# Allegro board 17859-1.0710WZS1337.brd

Outline 225.31 x 110 mm; copper layers: TOP, L2GND, L3, L4, L5VCC, L6, L7GND, BOTTOM. Coordinates in mm from the lower left corner of the outline.

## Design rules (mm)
constraint set DEFAULT: min track width 0.127, pair gap 0.102
net group 65982D_AUX-DIFF1: nets 65982D_AUXN 65982D_AUXP
net group BT_USB20_CON_N: nets BT_USB20_CON_N BT_USB20_N
net group BT_USB20_CON_P: nets BT_USB20_CON_P BT_USB20_P
net group CNV_WR_CLKN: nets CNV_WR_CLKN CNV_WR_CLKN_R
net group CNV_WR_CLKP: nets CNV_WR_CLKP CNV_WR_CLKP_R
net group CNV_WR_DN0: nets CNV_WR_DN0 CNV_WR_DN0_R
net group CNV_WR_DN1: nets CNV_WR_DN1 CNV_WR_DN1_R
net group CNV_WR_DP0: nets CNV_WR_DP0 CNV_WR_DP0_R
net group CNV_WR_DP1: nets CNV_WR_DP1 CNV_WR_DP1_R
net group CNV_WT_CLKN: nets CNV_WT_CLKN CNV_WT_CLKN_R
net group CNV_WT_CLKP: nets CNV_WT_CLKP CNV_WT_CLKP_R
net group CNV_WT_DN0: nets CNV_WT_DN0 CNV_WT_DN0_R
net group CNV_WT_DN1: nets CNV_WT_DN1 CNV_WT_DN1_R
net group CNV_WT_DP0: nets CNV_WT_DP0 CNV_WT_DP0_R
net group CNV_WT_DP1: nets CNV_WT_DP1 CNV_WT_DP1_R
net group DDR4_A_BA_40-MW: nets M_A_BA0 M_A_BA1
net group DDR4_A_BG_40-MW: nets M_A_BG0 M_A_BG1
net group DDR4_A_ODT: nets M_A_DIMA_ODT0 M_A_DIMA_ODT1
net group DDR4_B_BA_40-MW: nets M_B_BA0 M_B_BA1
net group DDR4_B_BG_40-MW: nets M_B_BG0 M_B_BG1
net group DDR4_B_ODT: nets M_B_DIMB_ODT0 M_B_DIMB_ODT1
net group DP2_AUX_CPU_N: nets DP2_AUX_C_N DP2_AUX_CPU_N
net group DP2_AUX_CPU_P: nets DP2_AUX_C_P DP2_AUX_CPU_P
net group DP2_DDI_TX_N0: nets DP2_DDI_TX_N0 DP2_DDI_TX_RE_C_N0
net group DP2_DDI_TX_N1: nets DP2_DDI_TX_N1 DP2_DDI_TX_RE_C_N1
net group DP2_DDI_TX_N2: nets DP2_DDI_TX_N2 DP2_DDI_TX_RE_C_N2
net group DP2_DDI_TX_N3: nets DP2_DDI_TX_N3 DP2_DDI_TX_RE_C_N3
net group DP2_DDI_TX_P0: nets DP2_DDI_TX_P0 DP2_DDI_TX_RE_C_P0
net group DP2_DDI_TX_P1: nets DP2_DDI_TX_P1 DP2_DDI_TX_RE_C_P1
net group DP2_DDI_TX_P2: nets DP2_DDI_TX_P2 DP2_DDI_TX_RE_C_P2
net group DP2_DDI_TX_P3: nets DP2_DDI_TX_P3 DP2_DDI_TX_RE_C_P3
net group EDP_AUX_CON_N: nets EDP_AUX_CON_N EDP_AUX_CPU_N
net group EDP_AUX_CON_P: nets EDP_AUX_CON_P EDP_AUX_CPU_P
net group EDP_TX_CON_N0: nets EDP_TX_CON_N0 EDP_TX_CPU_N0
net group EDP_TX_CON_N1: nets EDP_TX_CON_N1 EDP_TX_CPU_N1
net group EDP_TX_CON_P0: nets EDP_TX_CON_P0 EDP_TX_CPU_P0
net group EDP_TX_CON_P1: nets EDP_TX_CON_P1 EDP_TX_CPU_P1
net group GFX_PCIE_RX_C_N0: nets GFX_PCIE_RX_C_N0 GFX_PCIE_RX_N0
net group GFX_PCIE_RX_C_N1: nets GFX_PCIE_RX_C_N1 GFX_PCIE_RX_N1
net group GFX_PCIE_RX_C_N2: nets GFX_PCIE_RX_C_N2 GFX_PCIE_RX_N2
net group GFX_PCIE_RX_C_N3: nets GFX_PCIE_RX_C_N3 GFX_PCIE_RX_N3
net group GFX_PCIE_RX_C_P0: nets GFX_PCIE_RX_C_P0 GFX_PCIE_RX_P0
net group GFX_PCIE_RX_C_P1: nets GFX_PCIE_RX_C_P1 GFX_PCIE_RX_P1
net group GFX_PCIE_RX_C_P2: nets GFX_PCIE_RX_C_P2 GFX_PCIE_RX_P2
net group GFX_PCIE_RX_C_P3: nets GFX_PCIE_RX_C_P3 GFX_PCIE_RX_P3
net group GFX_PCIE_TX_C_N0: nets GFX_PCIE_TX_C_N0 GFX_PCIE_TX_N0
net group GFX_PCIE_TX_C_N1: nets GFX_PCIE_TX_C_N1 GFX_PCIE_TX_N1
net group GFX_PCIE_TX_C_N2: nets GFX_PCIE_TX_C_N2 GFX_PCIE_TX_N2
net group GFX_PCIE_TX_C_N3: nets GFX_PCIE_TX_C_N3 GFX_PCIE_TX_N3
net group GFX_PCIE_TX_C_P0: nets GFX_PCIE_TX_C_P0 GFX_PCIE_TX_P0
net group GFX_PCIE_TX_C_P1: nets GFX_PCIE_TX_C_P1 GFX_PCIE_TX_P1
net group GFX_PCIE_TX_C_P2: nets GFX_PCIE_TX_C_P2 GFX_PCIE_TX_P2
net group GFX_PCIE_TX_C_P3: nets GFX_PCIE_TX_C_P3 GFX_PCIE_TX_P3
net group GND: nets 65982D_GND MIC_GND
net group HDMI_DDI_TX_CMC_N0: nets HDMI_DDI_TX_CMC_N0 HDMI_DDI_TX_N0
net group HDMI_DDI_TX_CMC_N1: nets HDMI_DDI_TX_CMC_N1 HDMI_DDI_TX_N1
net group HDMI_DDI_TX_CMC_N2: nets HDMI_DDI_TX_CMC_N2 HDMI_DDI_TX_N2
net group HDMI_DDI_TX_CMC_N3: nets HDMI_DDI_TX_CMC_N3 HDMI_DDI_TX_N3
net group HDMI_DDI_TX_CMC_P0: nets HDMI_DDI_TX_CMC_P0 HDMI_DDI_TX_P0
net group HDMI_DDI_TX_CMC_P1: nets HDMI_DDI_TX_CMC_P1 HDMI_DDI_TX_P1
net group HDMI_DDI_TX_CMC_P2: nets HDMI_DDI_TX_CMC_P2 HDMI_DDI_TX_P2
net group HDMI_DDI_TX_CMC_P3: nets HDMI_DDI_TX_CMC_P3 HDMI_DDI_TX_P3
net group LAN_CLK_CPU-DIFF1: nets LAN_CLK_CPU_N LAN_CLK_CPU_P
net group LAN_PCIE_RX-DIFF1: nets LAN_PCIE_RX_N LAN_PCIE_RX_P
net group LAN_PCIE_TX_C_N: nets LAN_PCIE_TX_C_N LAN_PCIE_TX_N
net group LAN_PCIE_TX_C_P: nets LAN_PCIE_TX_C_P LAN_PCIE_TX_P
net group NTP_GFX_CLK_CPU-DIFF1: nets GFX_CLK_CPU_N GFX_CLK_CPU_P
net group NTP_M_A_CLK0-DIFF1: nets M_A_CLK0 M_A_CLK#0
net group NTP_M_A_CLK1-DIFF1: nets M_A_CLK1 M_A_CLK#1
net group NTP_M_A_DQS0-DIFF1: nets M_A_DQS_DN0 M_A_DQS_DP0
net group NTP_M_A_DQS1-DIFF1: nets M_A_DQS_DN1 M_A_DQS_DP1
net group NTP_M_A_DQS2-DIFF1: nets M_A_DQS_DN2 M_A_DQS_DP2
net group NTP_M_A_DQS3-DIFF1: nets M_A_DQS_DN3 M_A_DQS_DP3
net group NTP_M_A_DQS4-DIFF1: nets M_A_DQS_DN4 M_A_DQS_DP4
net group NTP_M_A_DQS5-DIFF1: nets M_A_DQS_DN5 M_A_DQS_DP5
net group NTP_M_A_DQS6-DIFF1: nets M_A_DQS_DN6 M_A_DQS_DP6
net group NTP_M_A_DQS7-DIFF1: nets M_A_DQS_DN7 M_A_DQS_DP7
net group NTP_M_B_CLK0-DIFF1: nets M_B_CLK0 M_B_CLK#0
net group NTP_M_B_CLK1-DIFF1: nets M_B_CLK1 M_B_CLK#1
net group NTP_M_B_DQS0-DIFF1: nets M_B_DQS_DN0 M_B_DQS_DP0
net group NTP_M_B_DQS1-DIFF1: nets M_B_DQS_DN1 M_B_DQS_DP1
net group NTP_M_B_DQS2-DIFF1: nets M_B_DQS_DN2 M_B_DQS_DP2
net group NTP_M_B_DQS3-DIFF1: nets M_B_DQS_DN3 M_B_DQS_DP3
net group NTP_M_B_DQS4-DIFF1: nets M_B_DQS_DN4 M_B_DQS_DP4
net group NTP_M_B_DQS5-DIFF1: nets M_B_DQS_DN5 M_B_DQS_DP5
net group NTP_M_B_DQS6-DIFF1: nets M_B_DQS_DN6 M_B_DQS_DP6
net group NTP_M_B_DQS7-DIFF1: nets M_B_DQS_DN7 M_B_DQS_DP7
net group NTP_VRAM_A_WCK01-DIFF1: nets FBA_WCK01 FBA_WCK01#
net group NTP_VRAM_A_WCK45-DIFF1: nets FBA_WCK45 FBA_WCK45#
net group NTP_VRAM_A_WCK67-DIFF1: nets FBA_WCK67 FBA_WCK67#
net group NTP_VRAM_CLK_A0-DIFF1: nets FBA_CLK0N FBA_CLK0P
net group NTP_VRAM_CLK_A1-DIFF1: nets FBA_CLK1N FBA_CLK1P
net group NTP_VRAM_S_WCK23-DIFF1: nets FBA_WCK23 FBA_WCK23#
net group PCIE_RCOMP-DIFF: nets PCIE_RCOMPN PCIE_RCOMPP
net group POWER_40M_POWER: nets HVA_GATE1 HVA_GATE2
net group POWER_160M: nets RT8812_PVCC VGACORE_VDD_SENSE_1
net group SENSE_VCORE-DIFF: nets VCC_SENSE VSS_SENSE
net group SENSE_VGT-DIFF: nets VCCGT_SENSE VSSGT_SENSE
net group SSD_PCIE_RX1-DIFF1: nets SSD_PCIE_RX_N1 SSD_PCIE_RX_P1
net group SSD_PCIE_TX_CON_N1: nets SSD_PCIE_TX_CON_N1 SSD_PCIE_TX_N1
net group SSD_PCIE_TX_CON_N2: nets SSD_PCIE_TX_CON_N2 SSD_PCIE_TX_N2
net group SSD_PCIE_TX_CON_N3: nets SSD_PCIE_TX_CON_N3 SSD_PCIE_TX_N3
net group SSD_PCIE_TX_CON_P1: nets SSD_PCIE_TX_CON_P1 SSD_PCIE_TX_P1
net group SSD_PCIE_TX_CON_P2: nets SSD_PCIE_TX_CON_P2 SSD_PCIE_TX_P2
net group SSD_PCIE_TX_CON_P3: nets SSD_PCIE_TX_CON_P3 SSD_PCIE_TX_P3
net group TBTA_SENSE-DIFF1: nets TBTA_SENSEN TBTA_SENSEP
net group THERM_7718-DIFF1: nets NCT7718_DXN NCT7718_DXP
net group TYPE_C_12M: nets USB1_CC1 USB1_CC2
net group USB1_PN1_R: nets USB1_PN1_R USB1_USB20_CON_N
net group USB1_PP1_R: nets USB1_PP1_R USB1_USB20_CON_P
net group USB1_SSRX_CMC_P1: nets USB1_SSRX_C_P1 USB1_SSRX_CMC_P1
net group USB1_SSRX_CMC_P2: nets USB1_SSRX_C_P2 USB1_SSRX_CMC_P2
net group USB1_SSTX_CMC_P1: nets USB1_SSTX_C_P1 USB1_SSTX_CMC_P1
net group USB1_SSTX_CMC_P2: nets USB1_SSTX_C_P2 USB1_SSTX_CMC_P2
net group USB1_USB30_RX_CON_N: nets USB1_USB30_RX_CON_N USB1_USB30_RX_N
net group USB1_USB30_TX_CMC_P: nets USB1_USB30_TX_CMC_P USB1_USB30_TX_P
net group USB2_USB30_TX_CMC_P: nets USB2_USB30_TX_CMC_P USB2_USB30_TX_P
net group USB4_USB30_RX_C_N: nets USB4_USB30_RX_C_N USB4_USB30_RX_N
net group USB4_USB30_RX_C_P: nets USB4_USB30_RX_C_P USB4_USB30_RX_P
net group USB4_USB30_TX_C_N: nets USB4_USB30_TX_C_N USB4_USB30_TX_N
net group USB4_USB30_TX_C_P: nets USB4_USB30_TX_C_P USB4_USB30_TX_P
net group VCCGT_ISUM_GA-DIFF1: nets PWR_VCCGT_ISUMN_GA PWR_VCCGT_ISUMP_GA
net group VCCSA_ISUM-DIFF1: nets PWR_VCCSA_ISUMN PWR_VCCSA_ISUMP
net group VCCSA_ISUM_R-DIFF1: nets PWR_VCCSA_ISUMN_R PWR_VCCSA_ISUMP_R
net group VCORE_ISUM_G-DIFF1: nets PWR_VCORE_ISUMN_G PWR_VCORE_ISUMP_G
net group WLAN_CLK_CPU-DIFF1: nets WLAN_CLK_CPU_N WLAN_CLK_CPU_P
net group WLAN_PCIE_RX-DIFF1: nets WLAN_PCIE_RX_N WLAN_PCIE_RX_P
net group WLAN_PCIE_TX_CON_N: nets WLAN_PCIE_TX_CON_N WLAN_PCIE_TX_N
net group WLAN_PCIE_TX_CON_P: nets WLAN_PCIE_TX_CON_P WLAN_PCIE_TX_P
net group XDP_TCLK-MWS: nets XDP_TCK_JTAGX XDP_TCLK
net group 27MHZ_CLK: nets 27MHZ_OUT_R
net group AUDIO_12MIL: nets CPVEE
net group AUDIO_BEEP_10MIL: nets AUD_HP1_JACK_L AUD_HP1_JACK_L1 AUD_HP1_JACK_R AUD_HP1_JACK_R1 AUD_HPJD_N AUD_PC_BEEP AUD_PC_BEEP_C AUD_PORTA_L_HPMIC1 AUD_PORTA_R_HPMIC1 AUD_SENSE AUD_VREF CBN CBP HDA_SPKR_R JACK_PLUG JACK_PLUG_DET KBC_BEEP_R LINE1-L_C LINE1-L_R LINE1_L LINE1_R LINE1_VREFO LINE1_VREFO_D1 LINE1_VREFO_D2 MIC2_VREFO SPKR
net group AUDIO_BEEP_40MIL: nets AUD_SPK_L+_C AUD_SPK_L-_C AUD_SPK_R+_C AUD_SPK_R-_C
net group AUDIO_DIGITAL_50-MWS: nets HPDIN
net group BOT_MUX_N: nets BOT_MUX_N_L
net group BOT_MUX_P: nets BOT_MUX_P_L
net group CCD_USB20_CON_N: nets CCD_USB20_N
net group CCD_USB20_CON_P: nets CCD_USB20_P
net group CFG_50-MWS: nets CFG4
net group CLK_50-MWS: nets GPIO0_CORE_VID GPIO11_LCD_VDD SUS_CLK
net group CLK_50R-MW: nets VIDEO_CLK_XTAL_SS
net group COMP_20MIL: nets CFG_RCOMP CPU_POPIRCOMP EMMC_RCOMP PCH_POPIRCOMP SD_RCOMP SM_RCOMP_0 SM_RCOMP_1 SM_RCOMP_2 USBCOMP XCLK_BIASREF
net group CPU_50-MWS: nets H_PROCHOT#_R PQ4405_3 PROCHOT#_CPU PROCHOT#_CPU_R PWR_CHG_PROCHOT#
net group CPU_50R-MW: nets PEX_TSTCLK_OUT PEX_TSTCLK_OUT# VGA_CORE_VID
net group DDR4_A_CMD_40-MW: nets M_A_A0 M_A_A1 M_A_A2 M_A_A3 M_A_A4 M_A_A5 M_A_A6 M_A_A7 M_A_A8 M_A_A9 M_A_A10 M_A_A11 M_A_A12 M_A_A13 M_A_A14 M_A_A15 M_A_A16 M_A_ACT_N M_A_ALERT_N M_A_PARITY
net group DDR4_A_DATA_00_50-MW: nets M_A_DQ0 M_A_DQ1 M_A_DQ2 M_A_DQ3 M_A_DQ4 M_A_DQ5 M_A_DQ6 M_A_DQ7
net group DDR4_A_DATA_01_50-MW: nets M_A_DQ8 M_A_DQ9 M_A_DQ10 M_A_DQ11 M_A_DQ12 M_A_DQ13 M_A_DQ14 M_A_DQ15
net group DDR4_A_DATA_02_50-MW: nets M_A_DQ16 M_A_DQ17 M_A_DQ18 M_A_DQ19 M_A_DQ20 M_A_DQ21 M_A_DQ22 M_A_DQ23
net group DDR4_A_DATA_03_50-MW: nets M_A_DQ24 M_A_DQ25 M_A_DQ26 M_A_DQ27 M_A_DQ28 M_A_DQ29 M_A_DQ30 M_A_DQ31
net group DDR4_A_DATA_04_50--MW: nets M_A_DQ32 M_A_DQ33 M_A_DQ34 M_A_DQ35 M_A_DQ36 M_A_DQ37 M_A_DQ38 M_A_DQ39
net group DDR4_A_DATA_05_50-MW: nets M_A_DQ40 M_A_DQ41 M_A_DQ42 M_A_DQ43 M_A_DQ44 M_A_DQ45 M_A_DQ46 M_A_DQ47
net group DDR4_A_DATA_06_50-MW: nets M_A_DQ48 M_A_DQ49 M_A_DQ50 M_A_DQ51 M_A_DQ52 M_A_DQ53 M_A_DQ54 M_A_DQ55
net group DDR4_A_DATA_07_50-MW: nets M_A_DQ56 M_A_DQ57 M_A_DQ58 M_A_DQ59 M_A_DQ60 M_A_DQ61 M_A_DQ62 M_A_DQ63
net group DDR4_B_CMD_40--MW: nets M_B_A0 M_B_A1 M_B_A2 M_B_A3 M_B_A4 M_B_A5 M_B_A6 M_B_A7 M_B_A8 M_B_A9 M_B_A10 M_B_A11 M_B_A12 M_B_A13 M_B_A14 M_B_A15 M_B_A16 M_B_ACT_N M_B_ALERT_N M_B_PARITY
net group DDR4_B_DATA_00_50-MW: nets M_B_DQ0 M_B_DQ1 M_B_DQ2 M_B_DQ3 M_B_DQ4 M_B_DQ5 M_B_DQ6 M_B_DQ7
net group DDR4_B_DATA_01_50-MW: nets M_B_DQ8 M_B_DQ9 M_B_DQ10 M_B_DQ11 M_B_DQ12 M_B_DQ13 M_B_DQ14 M_B_DQ15
net group DDR4_B_DATA_02_50-MW: nets M_B_DQ16 M_B_DQ17 M_B_DQ18 M_B_DQ19 M_B_DQ20 M_B_DQ21 M_B_DQ22 M_B_DQ23
net group DDR4_B_DATA_03_50-MW: nets M_B_DQ24 M_B_DQ25 M_B_DQ26 M_B_DQ27 M_B_DQ28 M_B_DQ29 M_B_DQ30 M_B_DQ31
net group DDR4_B_DATA_04_50-MW: nets M_B_DQ32 M_B_DQ33 M_B_DQ34 M_B_DQ35 M_B_DQ36 M_B_DQ37 M_B_DQ38 M_B_DQ39
net group DDR4_B_DATA_05_50-MW: nets M_B_DQ40 M_B_DQ41 M_B_DQ42 M_B_DQ43 M_B_DQ44 M_B_DQ45 M_B_DQ46 M_B_DQ47
net group DDR4_B_DATA_06_50-MW: nets M_B_DQ48 M_B_DQ49 M_B_DQ50 M_B_DQ51 M_B_DQ52 M_B_DQ53 M_B_DQ54 M_B_DQ55
net group DDR4_B_DATA_07_50-MW: nets M_B_DQ56 M_B_DQ57 M_B_DQ58 M_B_DQ59 M_B_DQ60 M_B_DQ61 M_B_DQ62 M_B_DQ63
net group DDR4_CKE_40-MW: nets M_A_CKE0 M_A_CKE1 M_A_CS#0 M_A_CS#1 M_B_CKE0 M_B_CKE1 M_B_CS#0 M_B_CS#1
net group DDR4_VREF: nets M_VREF_CA_DIMMA M_VREF_CA_DIMMB V_SM_VREF_CNTA V_SM_VREF_CNTB
net group ESPI: nets ESPI_ALERT# ESPI_CS# ESPI_RESET#
net group FAN_TACH: nets FAN1_TACH
net group FBA_VREF: nets FBA0_VREFC FBA1_VREFC FBA_VREF_FET_L
net group HDD_SATA_RX_CON_N: nets HDD_SATA_RX_N
net group HDD_SATA_RX_CON_P: nets HDD_SATA_RX_P
net group HDD_SATA_TX_CON_N: nets HDD_SATA_TX_N
net group HDD_SATA_TX_CON_P: nets HDD_SATA_TX_P
net group HDMI_I2C: nets HDMI_SCL_CON HDMI_SCL_CPU HDMI_SCL_R HDMI_SDA_CON HDMI_SDA_CPU HDMI_SDA_R
net group JTAG-MW: nets PCH_JTAG_TCK PCH_JTAG_TDI PCH_JTAG_TDO PCH_JTAG_TMS
net group KBC: nets KSI0 KSI1 KSI2 KSI3 KSI4 KSI5 KSI6 KSI7 KSO0 KSO1 KSO2 KSO3 KSO4 KSO5 KSO6 KSO7 KSO8 KSO9 KSO10 KSO11 KSO12 KSO13 KSO14 KSO15 KSO16
net group LCD_BKLT: nets BKLT_CTRL L_BKLT_CTRL LCD_BRIGHTNESS
net group LED: nets BAT1_LED# BAT2_LED# BATT_WHITE_LED# BATT_WHITE_LED_R# CAP_LED# CAP_LED#_D CHG_AMBER_LED#
net group LED_20MIL: nets AMBER_LED_BAT BAT_AMBER BAT_WHITE CAP_LED CAP_LED#_R CAP_LED_Q CHG_AMBER_LED_R# WHITE_LED_BAT
net group NTP_CNVI10: nets CNV_RGI_DT CNV_RGI_DT_R CNV_RGI_RSP CNV_RGI_RSP_R CNV_WT_RCOMP
net group NTP_OTHER_4MIL: nets CNV_BRI_DT CNV_BRI_DT_R CNV_BRI_RSP CNV_BRI_RSP_R
net group OTHER_4_Y10: nets 65982D_HRESET 65982D_MRESET 65982D_PRD_CC1 65982D_PRD_CC2 65982D_RESET_N CFG3 GPP_E3/CPU_GP0 GPU_PEX_RST# IST_TRIG PCH_DPWROK PLT_RST# PM_PCH_PWROK PM_RSMRST# PM_SLP_S0# PM_SLP_S3# PM_SLP_S4# PM_SLP_S5# SYS_PWROK TOUCH_PANEL_INTR# TP_LOCK# TP_RS
net group OTHER_4MIL: nets 1D2V_VTT_PWRGD 1D8V_AON_S0_DISCHG 1D8V_EN# 1D8V_EN_R# 1D8V_VGA_EN 1D8V_VGA_EN_OR 1D8V_VGA_EN_OR# 1D8V_VGA_EN_R 1D8V_VGA_S0_DISCHG 1D35V_PGOOD 1D35V_PGOOD_L 1D35V_VGA_EN 1D35V_VGA_EN# 1V_VGA_EN_B 1V_VGA_EN_OR 1V_VGA_EN_R 1V_VGA_EN_Y 1V_VGA_S0_DISCHG 1V_VGA_S0_PG 3.3V_WLAN_EN 3D3V_LDO_SET 3V_5V_DSW_OK 3V_5V_EN 3V_5V_POK 65982_GPIO1 65982_GPIO2 65982_GPIO3 65982_GPIO8 65982D_DBG_CTL1 65982D_DBG_CTL2 65982D_DEBUG3 65982D_DEBUG4 65982D_I2C_ADDR 65982D_LSTX_P2R 65982D_LSTX_R2P 65982D_PD_HPD 65982D_ROSC 65982D_SBU1 65982D_SBU2 65982D_UART_RX AC_PRESENT ACOK# ACOK_IN ACOK_IN_M AD_IA ALWON AUX_EN_WOWL AUX_ON BKLT_IN_EC BLON_OUT BLON_OUT_C BLUETOOTH_EN BLUETOOTH_EN_R BOARD_ID BOARD_ID1 BOARD_ID2 BOARD_ID_R BT_PCMFRM_CRF_RST_N BT_PCMFRM_CRF_RST_N_R BT_PCMOUT_CLKREQ0 BT_PCMOUT_CLKREQ0_R CAD_SNK CLK_PCIE_PEG_REQ# CLKIN_XTAL_LCP CLKIN_XTAL_LCP_R CLKRUN# CPU_D4_TP CPU_D6_TP CPU_DP_HPD_P CPU_SMB_ALERT# CPU_SMB_ALERT#_P0 CPU_SMB_ALERT#_P1 CTL1 CTL2 CTL3 DBC_EN_R DBC_PANEL_EN DGPU_PWR_EN DGPU_PWR_EN# DGPU_PWR_EN_Q DGPU_PWROK DGPU_PWROK_L DGPUHOT# DIMM1_SA0 DIMM1_SA1 DIMM1_SA2 DIMM2_SA0 DIMM2_SA1 DIMM2_SA2 DP1_HPD_CPU DP1_HPD_CPU_R DPEQ0_A1 DPEQ1 DVSS EDP_BKLT_CTRL EDP_HPD_CONN EDP_HPD_CPU EN_VCCSFR_OC EQ0 EQ1 EXT_PWR_GATE# FALL_INT2 FAN1_PWM FBA0_MF FBA0_SEN FBA1_MF FBA1_SEN FBA_DEBUG0 FBA_DEBUG1 FFS_INT1 FFS_INT2 FFS_INT2_Q FFS_INT2_Q_R FPR_SCAN# GC6_FB_EN GC6_FB_EN_GPU_L GC6_PWR_EN GC6_THM_DIS# GC6_THM_DIS#_EC GPD7 GPD11/LANPHYPC GPIO4_GC6_PWR_EN_GPU GPIO5_FRAME_LOCK# GPIO5_GC6_NVVDD_OR GPIO5_GC6_PWR_1V GPIO5_GC6_PWR_1V_A GPIO5_GC6_PWR_B GPIO5_GC6_PWR_EN GPIO8_OVERT GPIO8_OVERT#_EC GPIO9_ALERT GPIO10_FBVREF GPP_B22_GSPI1_MOSI GPP_E23 GPP_H17_STRAP GPP_H21 GPP_H23 GPPC_H18_BOOTMPC GPU_CLKREQ# GPU_PWR_LEVEL GSEN2_INT1_C GSEN2_INT1_ISH GSEN2_INT2_C GSEN2_INT2_ISH GSEN_INT1 GSEN_INT2 GYRO_DRDY GYRO_DRDY_ISH GYRO_INT GYRO_INT_C GYRO_INT_ISH GYRO_INT_P11 H_PECI HDD_DEVSLP HDD_DEVSLP_R HDMI_DET_CON HDMI_HPD_B HDMI_HPD_CPU HDMI_HPD_E HOST_DEBUG_TX HOST_DEBUG_TX_CON HW_ACAV_IN HW_ACAVIN_NB I2C_IRQ1# I2CEN I_ADP I_BATT IC_DELAY ICSP_CLK ICSP_CLR ICSP_DAT ILIM_HI ILIM_LO ILIM_SEL INPUT3VSEL INT2_SELECT INT#_TYPEC_R IR_CAM_DET# IRQ1# ISH_KB_DISABLE ITP_PMODE JIO3_PCIE_WAKE# JIO3_PCIE_WAKE#_R KB_DET# KB_DISABLE_CPU_R KB_LED_BL_DET KB_LED_DET_C KB_LED_PWM KBC_PWRBTN# KBC_PWRBTN#_C L_BKLT_EN L_BKLT_EN_L LAN_CLKREQ_CPU_N LCD_TST LCD_TST_C LCD_VCC_TEST_EN LCD_VCC_TEST_EN_R LID_CL_SIO# LID_CL_SIO_TAB# LID_CLOSE#_C M2_SSD_PEDET MASK_BASE_LEDS# MASK_SATA_LED# ME_FWP ME_FWP_SW MODEL_ID MSATA_RST# MUX_HPD_PD N12P_JTAG_TCK N12P_JTAG_TDI N12P_JTAG_TDO N12P_JTAG_TMS N12P_JTAG_TRST N12P_XTAL_OUTBUFF N198396033 N203186882 NAZ_GND1 NAZ_GND2 NB_MODE# NB_MUTE# NC_AUX_EN_WOWL_EC NRB_BIT P2800_VGA_DXN P2800_VGA_DXP PANEL_BKEN_EC PBAT_PRES1# PBAT_PRES# PCH_BATLOW# PCIE_WAKE# PCIE_WAKE#_CPU PD4403_A PD4403_K PD_OVP_TRIP_P1 PD_VBUS_C_CTRL1 PDB_R PEX_TERMP PIRQA# PLT_RST#_Q_TPM PM_LAN_ENABLE PM_LAN_ENABLE_R POWER_SW_IN# PQ3802_1 PQ4405_2 PQ4405_5 PQ4405_6 PQ4408_C PQ4408_E PRIM_PWRGD PROCHOT PROJECT_ID0 PROJECT_ID1 PROJECT_ID2 PROJECT_ID3 PS_ID_R PS_ID_R1 PS_ID_R2 PSID_DISABLE#_R_C PWR_1D35V_BYP PWR_1D35V_EN PWR_1D35V_PGOOD PWR_2D5V_EN PWR_3D3V_EN1 PWR_3V_PG PWR_5V_EN1 PWR_5V_EN1_R PWR_5V_PG PWR_CHG_ACOK PWR_VDDQ_EN PWR_VDDQ_PG PWR_VGA_CORE_PSI PWR_VGA_NVVDD_OR PWR_VGA_NVVDD_OR# PWR_VGA_NVVDD_PG PWR_VGA_NVVDD_PG# PWR_VGA_NVVDD_PG_OR PWR_VGA_S0_PG Q7601_G RESET_OUT# RESET_OUT#_G RTC_3P3_EN_G RTC_DET# RTC_RST# SATA_LED# SATA_LED#_D SENSOR_DB_DET# SIO_EXT_SMI# SIO_EXT_WAKE# SIO_PWRBTN# SKTOCC# SM_INTRUDER# SSD_CLKREQ_CPU_N SSD_DEVSLP SSD_DEVSLP_R SSD_LED# SSD_SCP# SSD_SCP#_M2 SSEQ0_A0 SSEQ1 STRAP_REF0_GND_N9 SYS_LED_MASK# SYS_LED_MASK#_R SYS_PEX_RST_MON# SYS_PEX_RST_MON_GPU# SYS_PRES1# SYSPWR_PRES TESTMODE THERMTRIP#_CPU TOUCH_DETECT TOUCH_PAD_INTR# TOUCH_PANEL_PD# TOUCH_REPORT_SW TP_EN# TP_RESET TP_WAKE_KBC# TPM_GPIO0 TPM_GPIO2 TPM_GPIO4 TPM_ID TPM_SPI_IRQ# TYPEC_DCIN_EN# UART1_CTS# UART1_RTS# UART_2_CRXD_DTXD UART_2_CRXD_DTXD_CON UART_2_CTXD_DRXD UART_2_CTXD_DRXD_CON UPD1_SMBINT# USB2_ID USB2_VBUSSENSE USB_EN# USB_OC0# USB_OC1# USB_OC2# USB_OC3# USB_POWERSHARE_VBUS_EN USB_PWR_EN# USB_PWR_SHR_EN_L# V0.85A_VID0 V0.85A_VID1 VBUS_P_CTRL VCCDSW_ON VCCIO_EN_R VCCSTG_EN_L VCI_IN1# VCREF0 VGA_CORE_DISCHG VR_EN VR_RDY VRALERT# VRAM_ID2 WIFI_RF_EN WIFI_RF_EN_R WLAN_CLKREQ_CPU_N WLAN_EN# WLAN_EN_R# XDP_CLK_CPU_N XDP_CLK_CPU_P XDP_DBRESET# XDP_PRDY# XDP_PREQ#
net group OTHER_I2C: nets DMIC_PCH_CLK DMIC_PCH_DATA SENSOR_I2C_SCL SENSOR_I2C_SDA
net group PD_I2C: nets I2C_CLK_PD I2C_CLK_PD_MUX I2C_DATA_PD I2C_DATA_PD_MUX
net group PECI_CPU: nets PECI_CPU
net group PLATFORM: nets 1D0V_S5_PWRGD 3V5V_S0_ON 3V_5V_POK# 3V_5V_POK_C DGPU_HOLD_RST# DGPU_PWR_EN_R EDP_VDD_EN EN1 EN2 GC6_FB_EN_GPU GC6_FB_EN_MCP GPIO1_GC6_FB_EN_GPU GPIO2_EVEN_GPU# GPIO6_VGA_CORE_PSI GPIO13_LCD_BLEN GPU_EVENT# GPU_EVENT_GPU# GPU_EVENT_MCP# GPU_PEX_RST_D# GPU_PEX_RST_HOLD GPU_PEX_RST_HOLD_GPU# H_CPUPWRGD LAN_WAKE# LANWAKE# LANWAKE#_IC LCDVDD_EN ME_SUS_PWR_ACK_R PCH_PLTRST# PCH_RSMRST# PM_RSMRST#_M PTP_DIS# PWR_1D0V_EN PWR_1D0V_PG PWR_1D8V_EN PWR_1D8V_POK PWR_2D5V_PG PWR_3D3V_EN Q501_G RSMRST_PWRGD# RTCRST_ON RUNPWROK SM_DRAMRST# SM_DRAMRST#_CPU SM_PGCNTL SM_PGCNTL_R SRTC_RST# STRAP0 STRAP1 STRAP2 STRAP3 STRAP4 SUSACK#_R TP_ON#_GATE TS#_DIMM0_1 TS#_DIMM1_1 VCCST_PWRGD VCCST_PWRGD_R VCCSTU_EN_R VGA_CORE_PSI
net group POWER_10M: nets 1D0V_VCCDSW 3D3V_GSEN2 3D3V_RTC_SYS 3D3V_TPM 3D3V_VCCDSW 3D3V_VCCPRTC 3V5V_CT1 3V5V_CT2 65982D_BUSPWR 65982D_LDO_1V8A 65982D_LDO_1V8D 65982D_LDO_BMC +3V_1D8V_AVDD +SDC_IN_SW AON_CT_2 BMON22 FB_CLAM FBA0_ZQ1 FBA1_ZQ3 LDO1_CAP LDO2_CAP LDO3_CAP LPS_SW LPS_SW_A LPS_SW_B LPS_SW_C LPS_SW_D MIC_CAP NZ_VHIO PD_VBUS_C_EN PD_VBUS_C_EN_A PQ4348_D PS_S3CNTRL PU4348_G PWR_VDDQ_TON PWR_VTT_EN Q6204_G USB1_SBU1 USB1_SBU2 V3D3_STB VCCRTCEXT VGA_CT_1 VGACORE_GND_SENSE_1
net group POWER_10M_POWER: nets +SDC_IN_SW_R1 AC_IN#_G AD_OFF_L DC_IN_OFF PD_VBUS_C_CTRL1_A PD_VBUS_C_CTRL1_R PQ4417_D PQ4418_2 PQ4418_3 PQ4418_5 PQ4418_6 PWR_1D0V_PFM PWR_1D0V_SS PWR_1D0V_TON PWR_1D35V_IMAX PWR_5V_EN PWR_CHG_ACIN PWR_CHG_ADP/ACIN PWR_CHG_AIN PWR_CHG_AIN_R PWR_CHG_AMON PWR_CHG_ASGATE/NTC PWR_CHG_BATGONE PWR_CHG_CMRSC PWR_CHG_COMP PWR_CHG_COMP_R PWR_CHG_CSIN PWR_CHG_CSIN_R PWR_CHG_CSIN_RR PWR_CHG_CSIP PWR_CHG_CSIP_R PWR_CHG_CSIP_RR PWR_CHG_CSON PWR_CHG_CSON_R PWR_CHG_CSON_RR PWR_CHG_CSOP PWR_CHG_CSOP_R PWR_CHG_CSOP_RR PWR_CHG_NTC PWR_CHG_OTGEN PWR_CHG_OTGPG PWR_CHG_PROCHOT#_R PWR_CHG_PROG PWR_VCCGT_COMP PWR_VCCGT_COMP1 PWR_VCCGT_FCCM# PWR_VCCGT_FCCM#_RA PWR_VCCGT_FCCM#_RB PWR_VCCGT_IMON PWR_VCCGT_ISUMN_GB PWR_VCCGT_ISUMN_P_1 PWR_VCCGT_ISUMN_P_2 PWR_VCCGT_ISUMN_RC PWR_VCCGT_ISUMNB PWR_VCCGT_ISUMP_GB PWR_VCCGT_NTC PWR_VCCGT_NTC1 PWR_VCCGT_PWMA PWR_VCCGT_PWMA_RA PWR_VCCGT_PWMB PWR_VCCGT_PWMB_RB PWR_VCCGT_RTN PWR_VCCSA_COMP PWR_VCCSA_COMP_RC PWR_VCCSA_FCCM PWR_VCCSA_IMON PWR_VCCSA_ISUMN_P_1 PWR_VCCSA_ISUMN_P_2 PWR_VCCSA_ISUMN_RC PWR_VCCSA_ISUMNB PWR_VCCSA_PWM PWR_VCCSA_RTN PWR_VCORE_COMP PWR_VCORE_COMP1 PWR_VCORE_FCCM# PWR_VCORE_FCCM#_R PWR_VCORE_IMON PWR_VCORE_ISUMN_P_1 PWR_VCORE_ISUMN_P_2 PWR_VCORE_ISUMN_RC PWR_VCORE_ISUMNA PWR_VCORE_NTC PWR_VCORE_NTC1 PWR_VCORE_PROG1 PWR_VCORE_PROG2 PWR_VCORE_PWM PWR_VCORE_PWM_R PWR_VCORE_RTN PWR_VCORE_VRHOT# PWR_VDDQ_CS PWR_VDDQ_VDDQ PWR_VGA_CORE_REFADJ PWR_VGA_CORE_REFIN PWR_VGA_CORE_REFIN_R PWR_VGA_CORE_SS PWR_VGA_CORE_SS/VSEN PWR_VGA_CORE_TON PWR_VGA_CORE_TON_1 PWR_VGA_CORE_VID PWR_VGA_CORE_VREF PWR_VGA_CORE_VREF_R PWR_VGA_CORE_VSNS PWR_VGA_CORE_VSNS/SS VBUS_P_CTRL_R VCCSA_SENSE VDD VSSSA_SENSE
net group POWER_15M: nets 3D3V_MUX 3D3V_TBT 3D3V_TP_S5_R 3D3V_TPM_VSB Q6205_Q
net group POWER_15M_POWER: nets PWR_1D0V_FB PWR_1D0V_FB_A PWR_1D35V_VFB PWR_1D35V_VFB1 PWR_3D3V_FB PWR_3D3V_FB2 PWR_3D3V_VOUT PWR_5V_FB PWR_5V_FB_A PWR_5V_VOUT PWR_VCCGT_FB PWR_VCCGT_FB1 PWR_VCCGT_FB2 PWR_VCCGT_FB_RC PWR_VCCSA_FB PWR_VCCSA_FB1 PWR_VCCSA_FB2 PWR_VCCSA_FB_RC PWR_VCORE_FB PWR_VCORE_FB1 PWR_VCORE_FB2 PWR_VCORE_FB_RC PWR_VDDQ_FB
net group POWER_20M: nets 1D0V_VCCA_XTAL 1D0V_VCCAMPHYPLL 1D8V_S5_KBC 1D24V_VCCDPHY_EC 1V_VCCSTG 3D3V_AUX_S5 3D3V_RTC 3D3V_TPM_VHIO 5V_AUX_S5 +RTC_VCC +V_VREF_PATH1 +V_VREF_PATH2 DGPU_PWR_1V GPCPLL_AVDD GPIO12_PWR_LEVEL N210032824 PWR_1V_FB PWR_VDDQ_VTTREF U5503_OUT
net group POWER_20M_POWER: nets 1D8V_CPVDD KB_BL_CTRL# PWR_3D3V_BOOT PWR_3D3V_BOOT_A PWR_5V_LDO PWR_5V_VCC PWR_CHG_ASGATE PWR_CHG_BGATE PWR_CHG_BGATE_22 PWR_CHG_BGATE_22_R PWR_CHG_BOOT1 PWR_CHG_DCIN PWR_CHG_DCIN_R PWR_CHG_NGATE PWR_CHG_VDDP PWR_VCORE_VIN PWR_VDDQ_BOOTA PWR_VDDQ_BOOTB PWR_VDDQ_SNB PWR_VDDQ_VCC VCCPD_VBUS_ACK
net group POWER_25M_POWER: nets PWR_1D0V_BT PWR_1D35V_BOOT_R PWR_5V_BOOT PWR_5V_BOOT_A PWR_CHG_ASGATE22 PWR_CHG_BGATE/HG2 PWR_CHG_BT1_R PWR_CHG_BT2_R PWR_CHG_LGATE2/ASGATE PWR_CHG_SNB PWR_VCCGT_BOOTA PWR_VCCGT_BOOTA_RC PWR_VCCGT_BOOTB PWR_VCCGT_BOOTB_RC PWR_VCCGT_BOOTRA PWR_VCCGT_BOOTRB PWR_VCCGT_SNB1 PWR_VCCGT_SNB2 PWR_VCCGT_VCCDA PWR_VCCGT_VCCDB PWR_VCCSA_BST PWR_VCCSA_BST_RC PWR_VCORE_BOOT PWR_VCORE_BOOT_RC PWR_VCORE_BOOTR PWR_VCORE_SNB PWR_VCORE_VCC PWR_VCORE_VCC_R PWR_VDDQ_BOOT PWR_VGA_CORE_BOOT1 PWR_VGA_CORE_BOOT1_1 PWR_VGA_CORE_BOOT2_1 PWR_VGA_CORE_LGATE1 PWR_VGA_CORE_LGATE2 PWR_VGA_CORE_UGATE1 PWR_VGA_CORE_UGATE2 PWR_VGA_SNUB1 PWR_VGA_SNUB2
net group POWER_40M: nets FB_CAL_PD_VDDQ FB_CAL_PU_GND FB_CAL_TERM_GND GPU_ROM VID_PLLVDD VID_PLLVDD_L
net group POWER_240M_POWER: nets 1D35V_VGA_S0_DISCHG
net group POWER_320M: nets 3D3V_PD
net group REF10M: nets VR_CAP
net group SENSOR: nets GSEN2_INT1 GSEN2_INT2 GSENSOR_CS GSENSOR_SDO SENSOR_I2C_SCL_2G SENSOR_I2C_SDA_2G
net group SIGNAL_V_F_4MIL: nets AC_DIS USB_OC2#_R USB_OC3#_R
net group SIGNAL_V_F_5MIL: nets CHGR_PSYS_IMVP Q4009_G SIO_SLP_A#
net group SIGNAL_V_F_10MIL-2: nets BEEP
net group SIGNAL_V_F_25MIL: nets PS_ID
net group SIGNAL_V_F_50OHM: nets PWR_VGA_CORE_EN STRAP5 STRAP5_L
net group SMBUS_10MIL: nets PBAT_SMBCLK1 PBAT_SMBDAT1 SUSCLK_WLAN
net group SMBUS_50-MWS: nets 65982D_DEBUG1 65982D_DEBUG2 CLK_TP_SIO CPU_DP2_CTRL_CLK CPU_DP2_CTRL_DATA CPU_I2C_SCL_ISH0 CPU_I2C_SCL_ISH1 CPU_I2C_SCL_P0 CPU_I2C_SCL_P1 CPU_I2C_SDA_ISH0 CPU_I2C_SDA_ISH1 CPU_I2C_SDA_P0 CPU_I2C_SDA_P1 CPU_SMB_SCL CPU_SMB_SCL_P0 CPU_SMB_SCL_P1 CPU_SMB_SDA CPU_SMB_SDA_P0 CPU_SMB_SDA_P1 DAT_TP_SIO DMIC_CLK_EDP DMIC_DATA_EDP DMIC_SCL_CODEC DMIC_SDA_CODEC GPU_I2CA_SCL GPU_I2CA_SDA GPU_ROM_SCLK GPU_THM_SMBCLK GPU_THM_SMBDAT I2C1_SCL_R I2C1_SDA_R I2CB_SCL I2CB_SDA I2CC_SCL I2CC_SDA PBAT_CHG_SMBCLK PBAT_CHG_SMBDAT PCH_SMBCLK PCH_SMBDATA SMBC_THERM_NV SMBD_THERM_NV SVID_CLK_CPU_R SVID_DATA_CPU_R THM_SML1_CLK THM_SML1_DATA TPCLK_C TPDATA_C TYPEC_SMBCLK TYPEC_SMBCLK_Q TYPEC_SMBDA TYPEC_SMBDA_Q
net group SPI_50-MWS: nets 65982D_EE_CLK 65982D_EE_CS_N 65982D_EE_DI 65982D_EE_DO GPU_ROM_SI GPU_ROM_SO PD_EE_WP_N PD_HOLD_N SIO_EXT_SCI# SIO_RCIN# SPI_CS_ROM_N0 SPI_IRQ#_TPM2
net group SSD_SATA_C_TX_N: nets SSD_SATA_C_TX_N SSD_SATA_TX_CON_N SSD_SATA_TX_N SSD_SATA_TX_N1
net group SSD_SATA_C_TX_P: nets SSD_SATA_C_TX_P SSD_SATA_TX_CON_P SSD_SATA_TX_P SSD_SATA_TX_P1
net group SSD_SATA_RX_CON_N: nets SSD_SATA_RX_CON_N SSD_SATA_RX_N SSD_SATA_RX_N1
net group SSD_SATA_RX_CON_P: nets SSD_SATA_RX_CON_P SSD_SATA_RX_P SSD_SATA_RX_P1
net group SVID-MW: nets PWR_VCORE_ALERT# PWR_VCORE_SCLK PWR_VCORE_SDIO SVID_ALERT#_CPU_R SVID_CLK_CPU SVID_DATA_CPU
net group T8-MW: nets CMP_VIN0 CMP_VIN0_R CMP_VOUT0 VD_IN1_C
net group TESTPD_4MIL: nets CATERR#_CPU FB_VREF TPM_GPIO1 TPM_GPIO3 TPM_PP
net group THERM_SHUTDOWN: nets ALERT# PURE_HW_SHUTDOWN# T_CRIT# THERM_SYS_SHDN#
net group TOP_MUX_N: nets TOP_MUX_N_L
net group TOP_MUX_P: nets TOP_MUX_P_L
net group USB1_SSRX_CMC_N1: nets USB1_SSRX_C_N1 USB1_SSRX_CMC_N1 USB1_SSRX_CON_N1
net group USB1_SSRX_CMC_N2: nets USB1_SSRX_C_N2 USB1_SSRX_CMC_N2 USB1_SSRX_CON_N2
net group USB1_SSTX_CMC_N1: nets USB1_SSTX_C_N1 USB1_SSTX_CMC_N1 USB1_SSTX_CON_N1
net group USB1_SSTX_CMC_N2: nets USB1_SSTX_C_N2 USB1_SSTX_CMC_N2 USB1_SSTX_CON_N2
net group USB1_USB30_RX_CON_P: nets USB1_USB30_RX_P
net group USB1_USB30_TX_CMC_N: nets USB1_USB30_TX_CMC_N USB1_USB30_TX_CON_N USB1_USB30_TX_N
net group USB2_USB20_CON_N: nets USB2_USB20_N
net group USB2_USB20_CON_P: nets USB2_USB20_P
net group USB2_USB30_RX_CON_N: nets USB2_USB30_RX_N
net group USB2_USB30_RX_CON_P: nets USB2_USB30_RX_P
net group USB2_USB30_TX_CMC_N: nets USB2_USB30_TX_CMC_N USB2_USB30_TX_CON_N USB2_USB30_TX_N
net group VCCGT_ISEN-DIFF1: nets PWR_VCCGT_ISEN1
net group VCCGT_ISUM-DIFF1: nets PWR_VCCGT_ISUMP
net group VRAM_A_DQ: nets FBA_CLK0_MIDPT FBA_CLK1_MIDPT FBA_D0 FBA_D1 FBA_D2 FBA_D3 FBA_D4 FBA_D5 FBA_D6 FBA_D7 FBA_D8 FBA_D9 FBA_D10 FBA_D11 FBA_D12 FBA_D13 FBA_D14 FBA_D15 FBA_D16 FBA_D17 FBA_D18 FBA_D19 FBA_D20 FBA_D21 FBA_D22 FBA_D23 FBA_D24 FBA_D25 FBA_D26 FBA_D27 FBA_D28 FBA_D29 FBA_D30 FBA_D31 FBA_D32 FBA_D33 FBA_D34 FBA_D35 FBA_D36 FBA_D37 FBA_D38 FBA_D39 FBA_D40 FBA_D41 FBA_D42 FBA_D43 FBA_D44 FBA_D45 FBA_D46 FBA_D47 FBA_D48 FBA_D49 FBA_D50 FBA_D51 FBA_D52 FBA_D53 FBA_D54 FBA_D55 FBA_D56 FBA_D57 FBA_D58 FBA_D59 FBA_D60 FBA_D61 FBA_D62 FBA_D63 FBA_DQM0 FBA_DQM1 FBA_DQM2 FBA_DQM3 FBA_DQM4 FBA_DQM5 FBA_DQM6 FBA_DQM7
net group VRAM_A_DQS: nets FBA_EDC0 FBA_EDC1 FBA_EDC2 FBA_EDC3 FBA_EDC4 FBA_EDC5 FBA_EDC6 FBA_EDC7
net group VRAM_CMD_45R-MWS: nets FBA_CMD0 FBA_CMD1 FBA_CMD2 FBA_CMD3 FBA_CMD4 FBA_CMD5 FBA_CMD6 FBA_CMD7 FBA_CMD8 FBA_CMD9 FBA_CMD10 FBA_CMD11 FBA_CMD12 FBA_CMD13 FBA_CMD14 FBA_CMD15 FBA_CMD16 FBA_CMD17 FBA_CMD18 FBA_CMD19 FBA_CMD20 FBA_CMD21 FBA_CMD22 FBA_CMD23 FBA_CMD24 FBA_CMD25 FBA_CMD26 FBA_CMD27 FBA_CMD28 FBA_CMD29 FBA_CMD30 FBA_CMD31
net group VREF: nets 1V_VREF_CPU
net group XDP-MW: nets SVID_ALERT#_CPU XDP_TDI XDP_TDO_CPU XDP_TMS XDP_TRST# XTAL_KBC_2
net group XDP_BPM-MW: nets BPM_CPU_N0 BPM_CPU_N1 BPM_CPU_N2 BPM_CPU_N3
net group XTAL-MW: nets MEC_XTAL1_R MEC_XTAL2 XTL_24M_X1_CPU XTL_24M_X1_R XTL_24M_X2_CPU XTL_24M_X2_R XTL_32K_X1_CPU XTL_32K_X2_CPU
nets with their own width: min track width 0.254; nets 1D2V_S3

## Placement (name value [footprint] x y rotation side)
AFTP2501  AFTE14P-GP  [AFTE14P-75]  207.33 7.9 0 top
AFTP2502  AFTE14P-GP  [AFTE14P-75]  208.12 11.99 0 top
AFTP2601  AFTE14P-GP  [AFTE14P-75]  216.58 64.16 0 top
AFTP2602  AFTE14P-GP  [AFTE14P-75]  218.59 63.68 0 top
AFTP2603  AFTE14P-GP  [AFTE14P-75]  216.58 66.37 0 top
AFTP2604  AFTE14P-GP  [AFTE14P-75]  219.65 59.64 0 top
AFTP2901  AFTE14P-GP  [AFTE14P-75]  18.99 9.76 90 top
AFTP2902  AFTE14P-GP  [AFTE14P-75]  17.09 9.45 90 top
AFTP2903  AFTE14P-GP  [AFTE14P-75]  21.08 10.85 0 top
AFTP2904  AFTE14P-GP  [AFTE14P-75]  21.38 8.89 0 top
AFTP3501  AFTE14P-GP  [AFTE14P-75]  15.01 28.93 180 top
AFTP3504  AFTE14P-GP  [AFTE14P-75]  15.67 48.21 180 top
AFTP3505  AFTE14P-GP  [AFTE14P-75]  17.47 43.97 90 top
AFTP3506  AFTE14P-GP  [AFTE14P-75]  15.64 43.39 90 top
AFTP4301  AFTE14P-GP  [AFTE14P-75]  26.31 91.8 0 top
AFTP4302  AFTE14P-GP  [AFTE14P-75]  25.57 93.65 0 top
AFTP4303  AFTE14P-GP  [AFTE14P-75]  32.38 94.21 0 top
AFTP4304  AFTE14P-GP  [AFTE14P-75]  27.83 95.76 90 top
AFTP4305  AFTE14P-GP  [AFTE14P-75]  28.52 93.86 0 top
AFTP4306  AFTE14P-GP  [AFTE14P-75]  123.23 11.76 0 top
AFTP4307  AFTE14P-GP  [AFTE14P-75]  108.35 11.99 0 top
AFTP4308  AFTE14P-GP  [AFTE14P-75]  109.29 10.01 0 top
AFTP4309  AFTE14P-GP  [AFTE14P-75]  112.67 13.9 0 top
AFTP4310  AFTE14P-GP  [AFTE14P-75]  114.57 13.9 0 top
AFTP4311  AFTE14P-GP  [AFTE14P-75]  116.5 13.95 0 top
AFTP4312  AFTE14P-GP  [AFTE14P-75]  118.66 12.78 0 top
AFTP4313  AFTE14P-GP  [AFTE14P-75]  120.42 13.87 0 top
AFTP4314  AFTE14P-GP  [AFTE14P-75]  122.4 13.87 0 top
AFTP4315  AFTE14P-GP  [AFTE14P-75]  110.75 13.92 0 top
AFTP4316  AFTE14P-GP  [AFTE14P-75]  30.4 94.52 0 top
AFTP6001  AFTE14P-GP  [AFTE14P-75]  186.84 14.99 270 top
AFTP6101  AFTE14P-GP  [AFTE14P-75]  214.75 52.73 0 top
AFTP6105  AFTE14P-GP  [AFTE14P-75]  197.1 58.91 0 top
AFTP6106  AFTE14P-GP  [AFTE14P-75]  198.29 55.02 180 top
AFTP6107  AFTE14P-GP  [AFTE14P-75]  200.27 55.17 180 top
AFTP6108  AFTE14P-GP  [AFTE14P-75]  204.9 57.86 180 top
AFTP6109  AFTE14P-GP  [AFTE14P-75]  210.94 60.86 0 top
AFTP6110  AFTE14P-GP  [AFTE14P-75]  212.62 61.78 0 top
AFTP6301  AFTE14P-GP  [AFTE14P-75]  220.69 8.87 90 top
AFTP6303  AFTE14P-GP  [AFTE14P-75]  209.21 4.27 90 top
AFTP6304  AFTE14P-GP  [AFTE14P-75]  218.03 20.65 90 top
AFTP6502  AFTE14P-GP  [AFTE14P-75]  70.25 6.94 0 top
AFTP6503  AFTE14P-GP  [AFTE14P-75]  82.39 11.18 0 top
AFTP6505  AFTE14P-GP  [AFTE14P-75]  76.14 6.94 0 top
AFTP6506  AFTE14P-GP  [AFTE14P-75]  83.94 6.71 180 top
AFTP6507  AFTE14P-GP  [AFTE14P-75]  69.69 8.84 0 top
AFTP6508  AFTE14P-GP  [AFTE14P-75]  79.24 9.3 0 top
AFTP6510  AFTE14P-GP  [AFTE14P-75]  78.02 11.25 0 top
AFTP6511  AFTE14P-GP  [AFTE14P-75]  63.98 9.43 0 top
AFTP6512  AFTE14P-GP  [AFTE14P-75]  73.53 8.82 0 top
AFTP6513  AFTE14P-GP  [AFTE14P-75]  67.79 8.89 0 top
AFTP6515  AFTE14P-GP  [AFTE14P-75]  80.11 6.63 0 top
AFTP6516  AFTE14P-GP  [AFTE14P-75]  82.01 6.68 0 top
AFTP6517  AFTE14P-GP  [AFTE14P-75]  75.66 10.85 0 top
AFTP6518  AFTE14P-GP  [AFTE14P-75]  75.43 8.84 0 top
AFTP6519  AFTE14P-GP  [AFTE14P-75]  62.07 9.4 0 top
AFTP6520  AFTE14P-GP  [AFTE14P-75]  78.15 6.71 0 top
AFTP6521  AFTE14P-GP  [AFTE14P-75]  66.36 6.96 0 top
AFTP6522  AFTE14P-GP  [AFTE14P-75]  71.6 8.79 180 top
AFTP6523  AFTE14P-GP  [AFTE14P-75]  64.51 7.52 0 top
AFTP6524  AFTE14P-GP  [AFTE14P-75]  179.5 15.24 180 top
AFTP6525  AFTE14P-GP  [AFTE14P-75]  177.24 15.73 0 top
AFTP6526  AFTE14P-GP  [AFTE14P-75]  177.92 13.92 0 top
AFTP6527  AFTE14P-GP  [AFTE14P-75]  175.99 14.23 0 top
AFTP6528  AFTE14P-GP  [AFTE14P-75]  174.64 12.78 0 top
AFTP6529  AFTE14P-GP  [AFTE14P-75]  180.61 5.59 0 top
AFTP6530  AFTE14P-GP  [AFTE14P-75]  180 13.31 0 top
AFTP6531  AFTE14P-GP  [AFTE14P-75]  86.13 4.63 180 top
AFTP6532  AFTE14P-GP  [AFTE14P-75]  83.26 9.02 180 top
AFTP6533  AFTE14P-GP  [AFTE14P-75]  65.86 8.94 0 top
AFTP6534  AFTE14P-GP  [AFTE14P-75]  74.21 6.86 0 top
AFTP6535  AFTE14P-GP  [AFTE14P-75]  81.35 9.2 180 top
AFTP6536  AFTE14P-GP  [AFTE14P-75]  72.21 6.94 0 top
AFTP6537  AFTE14P-GP  [AFTE14P-75]  60.27 4.42 180 top
AFTP6538  AFTE14P-GP  [AFTE14P-75]  77.34 9.1 0 top
AFTP6539  AFTE14P-GP  [AFTE14P-75]  79.98 11.31 180 top
AFTP6540  AFTE14P-GP  [AFTE14P-75]  68.32 6.99 0 top
AFTP6565  AFTE14P-GP  [AFTE14P-75]  175.74 17.05 0 top
AFTP6605  AFTE14P-GP  [AFTE14P-75]  99 13.69 0 top
AFTP6606  AFTE14P-GP  [AFTE14P-75]  102.53 12.14 0 top
AFTP6607  AFTE14P-GP  [AFTE14P-75]  100.48 12.35 0 top
AFTP6608  AFTE14P-GP  [AFTE14P-75]  196.36 54.77 0 top
AUD1  AUDIO-JK662-GP-U  [2SJ3166-007111F-U]  1.86 7.15 90 bottom
BATT1  ETY-CON10-33-GP  [3806K-F10N-03L]  119.51 12.05 180 bottom
BS2  STF237R113H62-4-GP  [STF237R113H62]  7.71 98.5 180 bottom
C801  SC1U10V2KX-1DLGP  [C402H22]  117.8 77.73 90 top
C802  SC1U25V3KX-1-DLGP  [C603H36]  89.86 93.07 0 bottom
C803  SC1U10V2KX-1DLGP  [C402H22]  112.39 68.28 90 top
C804  SC1U10V2KX-1DLGP  [C402H22]  82.06 18.09 0 top
C805  SCD1U16V2KX-3DLGP  [C402H22]  119.12 78.51 270 top
C806  SC1U10V2KX-1DLGP  [C402H22]  117.98 78.95 0 top
C1102  SC1U10V2KX-1DLGP  [C402H22]  82.87 78.34 270 top
C1103  SC1U10V2KX-1DLGP  [C402H22]  91.92 79.17 90 top
C1104  SC1U10V2KX-1DLGP  [C402H22]  82.87 79.1 270 top
C1105  SC1U25V3KX-1-DLGP  [C603H36]  83.89 72.49 0 top
C1106  SC1U10V2KX-1DLGP  [C402H22]  88.84 71.94 0 top
C1107  SC1U10V2KX-1DLGP  [C402H22]  88.08 71.94 0 top
C1108  SC1U10V2KX-1DLGP  [C402H22]  160.98 55.96 0 top
C1109  SC1U25V3KX-1-DLGP  [C603H36]  159.25 55.65 0 top
C1110  SC1U25V3KX-1-DLGP  [C603H36]  158.08 55.65 0 top
C1111  SC1U10V2KX-1DLGP  [C402H22]  160.22 55.96 0 top
C1112  SC22U6D3V3MX-1-DL-GP  [C603H40]  114.52 76.02 270 top
C1113  SC22U6D3V3MX-1-DL-GP  [C603H40]  145.59 85.52 270 top
C1114  SC1U25V3KX-1-DLGP  [C603H36]  156.31 56.31 90 top
C1115  SC22U6D3V3MX-1-DL-GP  [C603H40]  114.52 77.29 270 top
C1116  SC1U10V2KX-1DLGP  [C402H22]  156.99 57.41 90 top
C1117  SC1U25V3KX-1-DLGP  [C603H36]  156.81 58.45 90 top
C1118  SC22U6D3V3MX-1-DL-GP  [C603H40]  114.52 74.75 270 top
C1119  SC1U10V2KX-1DLGP  [C402H22]  148.13 52.89 270 top
C1120  SC10U6D3V3MX-DL-GP  [C603H36]  148.28 54.99 90 bottom
C1121  SC1U10V2KX-1DLGP  [C402H22]  148.74 53.65 270 top
C1122  SC22U6D3V3MX-1-DL-GP  [C603H40]  144.88 68.4 0 top
C1123  SC10U6D3V3MX-DL-GP  [C603H36]  145.59 84.25 270 top
C1128  SC22U6D3V3MX-1-DL-GP  [C603H40]  114.4 105.44 270 bottom
C1129  SC22U6D3V3MX-1-DL-GP  [C603H40]  110.51 107.7 90 bottom
C1130  SC22U6D3V3MX-1-DL-GP  [C603H40]  98.75 45.65 0 top
C1131  SC22U6D3V3MX-1-DL-GP  [C603H40]  103.83 45.65 0 top
C1132  SC22U6D3V3MX-1-DL-GP  [C603H40]  100.02 45.65 0 top
C1133  SC22U6D3V3MX-1-DL-GP  [C603H40]  160.65 55.58 180 bottom
C1134  SC22U6D3V3MX-1-DL-GP  [C603H40]  158.03 55.57 180 bottom
C1135  SC22U6D3V3MX-1-DL-GP  [C603H40]  159.32 55.57 180 bottom
C1136  SC10U6D3V3MX-DL-GP  [C603H36]  102.56 45.65 0 top
C1137  SC10U6D3V3MX-DL-GP  [C603H36]  101.29 45.65 0 top
C1138  SC10U6D3V3MX-DL-GP  [C603H36]  105.1 45.65 0 top
C1139  SCD1U16V2KX-3DLGP  [C402H22]  95.17 45.63 0 top
C1140  SCD1U16V2KX-3DLGP  [C402H22]  94.39 45.63 0 top
C1141  SCD1U16V2KX-3DLGP  [C402H22]  93.62 45.62 0 top
C1142  SCD1U16V2KX-3DLGP  [C402H22]  97.61 45.62 0 top
C1202  SC10U6D3V3MX-DL-GP  [C603H36]  54.86 25.89 90 top
C1203  SC10U6D3V3MX-DL-GP  [C603H36]  54.86 24.62 90 top
C1204  SC10U6D3V3MX-DL-GP  [C603H36]  79.17 27.56 0 top
C1205  SC10U6D3V3MX-DL-GP  [C603H36]  67.96 19.76 0 top
C1206  SC10U6D3V3MX-DL-GP  [C603H36]  47.26 18.93 0 top
C1207  SC1U10V2KX-1DLGP  [C402H22]  101.85 27.64 0 top
C1208  SC10U6D3V3MX-DL-GP  [C603H36]  80.46 27.56 0 top
C1209  SC10U6D3V3MX-DL-GP  [C603H36]  66.69 19.76 0 top
C1210  SC10U6D3V3MX-DL-GP  [C603H36]  54.86 23.35 90 top
C1211  SC4D7U6D3V2MX-1-GP  [C402H22]  99.08 27.59 0 top
C1212  SC4D7U6D3V2MX-1-GP  [C402H22]  98.32 27.59 0 top
C1213  SC1U10V2KX-1DLGP  [C402H22]  102.97 27.99 90 top
C1214  SC1U10V2KX-1DLGP  [C402H22]  82.37 25.35 0 top
C1215  SC1U10V2KX-1DLGP  [C402H22]  58.34 20.02 0 top
C1216  SC1U10V2KX-1DLGP  [C402H22]  59.73 20.02 0 top
C1217  SC1U10V2KX-1DLGP  [C402H22]  87.47 21.72 180 top
C1218  SC1U10V2KX-1DLGP  [C402H22]  61.26 20.02 0 top
C1219  SC1U10V2KX-1DLGP  [C402H22]  36.42 21.75 180 top
C1220  SC1U10V2KX-1DLGP  [C402H22]  62.66 20.02 0 top
C1221  SC1U10V2KX-1DLGP  [C402H22]  44.22 18.62 0 top
C1222  SCD022U16V2KX-3DLGP  [C402H22]  70.91 19.13 90 top
C1223  SC2D2U10V3KX-1DLGP-U  [C603H36]  94.15 27.64 270 top
C1224  SC4D7U6D3V2MX-1-GP  [C402H22]  101.21 23.12 90 top
C1225  SC4D7U6D3V3KX-DLGP  [C603H36]  98.22 22.38 270 top
C1226  SC1U10V2KX-1DLGP  [C402H22]  98.55 21.08 270 top
C1227  SC4D7U6D3V3KX-DLGP  [C603H36]  101.26 21.34 90 top
C1228  SCD1U16V2KX-3DLGP  [C402H22]  94.58 26.6 270 top
C1229  SCD1U25V2KX-1-DL-GP  [C402H22]  72.31 20.2 180 top
C1230  SC4D7U6D3V2MX-1-GP  [C402H22]  101.21 23.9 90 top
C1231  SC4D7U6D3V3KX-DLGP  [C603H36]  100.81 27.54 0 top
C1232  SC4D7U6D3V2MX-1-GP  [C402H22]  97.56 27.59 0 top
C1233  SC1U10V2KX-1DLGP  [C402H22]  101.21 22.35 90 top
C1301  SCD1U25V2KX-1-DL-GP  [C402H22]  151.17 18.62 90 top
C1303  SC10U6D3V3MX-DL-GP  [C603H36]  112.97 20.83 180 top
C1304  SC10U6D3V3MX-DL-GP  [C603H36]  139.03 29.67 180 top
C1305  SC10U6D3V3MX-DL-GP  [C603H36]  127.98 28.1 0 top
C1306  SC10U6D3V3MX-DL-GP  [C603H36]  148.89 29.72 180 top
C1307  SC10U6D3V3MX-DL-GP  [C603H36]  152.88 29.72 180 top
C1308  SC10U6D3V3MX-DL-GP  [C603H36]  118.64 28.12 0 top
C1309  SC10U6D3V3MX-DL-GP  [C603H36]  140.33 29.67 180 top
C1310  SC10U6D3V3MX-DL-GP  [C603H36]  144.93 29.72 180 top
C1311  SC4D7U6D3V3KX-DLGP  [C603H36]  175.64 29.57 180 top
C1312  SC4D7U6D3V2MX-1-GP  [C402H22]  174.64 29.44 180 top
C1313  SC1U10V2KX-1DLGP  [C402H22]  173.83 29.44 180 top
C1314  SC1U10V2KX-1DLGP  [C402H22]  177.72 27.13 90 top
C1315  SC1U10V2KX-1DLGP  [C402H22]  135.05 21.03 180 top
C1316  SC1U10V2KX-1DLGP  [C402H22]  166.29 19.94 0 top
C1317  SC1U10V2KX-1DLGP  [C402H22]  153.97 21.85 180 top
C1318  SC1U10V2KX-1DLGP  [C402H22]  123.59 20.91 180 top
C1319  SC1U10V2KX-1DLGP  [C402H22]  156.66 20.12 0 top
C1320  SC1U10V2KX-1DLGP  [C402H22]  132.58 20.35 180 top
C1321  SC1U10V2KX-1DLGP  [C402H22]  131.54 20.35 180 top
C1322  SC1U10V2KX-1DLGP  [C402H22]  170.86 28.78 180 top
C1323  SCD022U16V2KX-3DLGP  [C402H22]  149.52 18.62 270 top
C1324  SC10U6D3V3MX-DL-GP  [C603H36]  175.15 21.19 270 top
C1325  SC10U6D3V3MX-DL-GP  [C603H36]  175.15 19.92 270 top
C1326  SC1U10V2KX-1DLGP  [C402H22]  174.82 22.23 270 top
C1327  SC1U10V2KX-1DLGP  [C402H22]  174.82 22.99 270 top
C1328  SCD1U16V2KX-3DLGP  [C402H22]  155.9 19.46 180 top
C1329  SC2D2U10V3KX-1DLGP-U  [C603H36]  152.57 17.73 0 top
C1330  SC4D7U6D3V2MX-1-GP  [C402H22]  177.72 27.92 90 top
C1331  SC4D7U6D3V3KX-GP  [C603H36]  177.44 28.96 90 top
C1605  SCD22U10V2KX-1GP  [C402H22]  120.63 89.13 180 bottom
C1606  SCD22U10V2KX-1GP  [C402H22]  119.87 89.13 180 bottom
C1607  SCD22U10V2KX-1GP  [C402H22]  119.11 89.13 180 bottom
C1608  SCD22U10V2KX-1GP  [C402H22]  118.34 89.13 180 bottom
C1609  SCD22U10V2KX-1GP  [C402H22]  117.58 89.13 180 bottom
C1610  SCD22U10V2KX-1GP  [C402H22]  116.82 89.13 180 bottom
C1611  SCD22U10V2KX-1GP  [C402H22]  116.06 89.13 180 bottom
C1612  SCD22U10V2KX-1GP  [C402H22]  115.3 89.13 180 bottom
C1613  SCD1U16V2KX-3DLGP  [C402H22]  114.53 89.13 180 bottom
C1614  SCD1U16V2KX-3DLGP  [C402H22]  113.77 89.13 180 bottom
C1701  SC220P50V2KX-3DLGP  [C402H22]  131.59 44.96 90 top
C1710  SCD47U25V3KX-1-DL-GP  [C603H36]  115.89 42.17 90 top
C1711  SCD1U16V2KX-3DLGP  [C402H22]  111.98 93.63 180 top
C1803  SC15P50V2JN-DL-GP  [C402H22]  113.76 52.68 90 top
C1804  SC15P50V2JN-DL-GP  [C402H22]  110.61 52.68 270 top
C1805  SC1U10V2KX-1DLGP  [C402H22]  127.45 42.62 90 top
C1806  SC1U10V2KX-1DLGP  [C402H22]  127.32 44.81 90 top
C1807  SC15P50V2JN-DL-GP  [C402H22]  137.61 78.29 0 bottom
C1808  SC15P50V2JN-DL-GP  [C402H22]  137.61 79.76 180 bottom
C2201  SCD1U16V2KX-3DLGP  [C402H22]  115.03 73.74 270 top
C2202  SC1U10V2KX-1DLGP  [C402H22]  123.79 74.7 180 top
C2203  SC1U10V2KX-1DLGP  [C402H22]  122.3 73.56 270 top
C2204  SC1U10V2KX-1DLGP  [C402H22]  121.61 74.68 180 top
C2205  SC1U10V2KX-1DLGP  [C402H22]  123.01 74.7 180 top
C2206  SCD1U16V2KX-3DLGP  [C402H22]  145.33 87.25 270 top
C2207  SCD1U16V2KX-3DLGP  [C402H22]  145.33 86.49 270 top
C2208  SC22U6D3V3MX-1-DL-GP  [C603H40]  118.92 93.4 180 top
C2209  SC1U25V3KX-1-DLGP  [C603H36]  120.13 93.49 180 top
C2210  SC1U10V2KX-1DLGP  [C402H22]  129.18 74.4 270 top
C2211  SC1U10V2KX-1DLGP  [C402H22]  129.23 70.23 270 top
C2212  SC1U10V2KX-1DLGP  [C402H22]  148.74 54.41 270 top
C2213  SC1U10V2KX-1DLGP  [C402H22]  118.59 68.27 90 top
C2214  SC1U25V3KX-1-DLGP  [C603H36]  118.06 75.11 270 top
C2215  SC1U10V2KX-1DLGP  [C402H22]  119.98 75.06 90 top
C2216  SC1U10V2KX-1DLGP  [C402H22]  122.88 77.32 180 top
C2217  SC1U10V2KX-1DLGP  [C402H22]  156.13 55.3 90 top
C2218  SC4D7U6D3V3KX-DLGP  [C603H36]  128.82 69.19 270 top
C2219  SC1U10V2KX-1DLGP  [C402H22]  129.34 80.34 270 top
C2220  SC22U6D3V3MX-1-DL-GP  [C603H40]  118.18 76.74 270 top
C2221  SCD1U16V2KX-3DLGP  [C402H22]  117.06 72.75 180 top
C2222  SC1U10V2KX-1DLGP  [C402H22]  116.3 72.75 180 top
C2223  SC1U10V2KX-1DLGP  [C402H22]  123.64 76.43 0 top
C2224  SC1U10V2KX-1DLGP  [C402H22]  118.26 67.51 90 top
C2405  SC100P50V2JN-3GP  [C402H22]  28.03 36.38 270 top
C2406  SCD1U25V2KX-1-DL-GP  [C402H22]  29.89 35.13 270 top
C2407  SCD1U25V2KX-1-DL-GP  [C402H22]  36.54 34.19 90 top
C2408  SCD1U25V2KX-1-DL-GP  [C402H22]  38.48 31.75 270 top
C2409  SCD01U50V2KX-1DLGP  [C402H22]  52.72 48.64 0 top
C2410  SCD1U25V2KX-1-DL-GP  [C402H22]  50.08 47.2 90 top
C2411  SCD1U25V2KX-1-DL-GP  [C402H22]  48.89 38.31 0 top
C2412  SCD1U25V2KX-1-DL-GP  [C402H22]  49.68 44.91 90 top
C2413  SCD1U25V2KX-1-DL-GP  [C402H22]  27.6 48.92 0 top
C2414  SCD1U25V2KX-1-DL-GP  [C402H22]  43.5 54.16 180 top
C2416  SCD1U25V2KX-1-DL-GP  [C402H22]  39.21 29.21 90 top
C2418  SC1U10V2KX-1GP  [C402H22]  49.7 44.15 90 top
C2420  SCD1U25V2KX-1-DL-GP  [C402H22]  34.31 33.58 0 top
C2421  SCD1U25V2KX-1-DL-GP  [C402H22]  39.21 30 90 top
C2422  SCD1U25V2KX-1-DL-GP  [C402H22]  40.89 32.39 0 top
C2423  SCD1U25V2KX-1-DL-GP  [C402H22]  39.59 53.5 90 top
C2424  SC18P50V2JN-1-GP  [C402H22]  47.02 33.05 270 top
C2425  SC18P50V2JN-1-GP  [C402H22]  43.89 33.07 90 top
C2426  SC2D2U10V3KX-1DLGP-U  [C603H36]  50.18 34.75 90 top
C2428  SCD1U25V2KX-1-DL-GP  [C402H22]  42.54 33.23 0 top
C2429  SCD1U25V2KX-1-DL-GP  [C402H22]  28.49 42.88 270 top
C2430  SC2200P50V2KX-2GP  [C402H22]  29.15 51.31 270 bottom
C2431  SC2200P50V2KX-2GP  [C402H22]  32.15 34.29 0 top
C2436  SC2200P50V2KX-2GP  [C402H22]  26.89 26.29 180 top
C2501  SC10U10V3MX-1-GP  [C603H36]  186.94 28.78 90 bottom
C2502  SCD1U16V2KX-3DLGP  [C402H22]  184.93 37.42 0 top
C2503  SCD47U25V3KX-1-DL-GP  [C603H36]  209.37 17.83 0 top
C2517  SCD022U16V2KX-3DLGP  [C402H22]  210.15 23.62 90 top
C2525  SC1U10V2KX-1GP  [C402H22]  213.35 25.05 0 top
C2601  SC10U6D3V3MX-DL-GP  [C603H36]  168.83 106.12 90 top
C2602  SCD1U16V2KX-3DLGP  [C402H22]  168.95 107.14 90 top
C2603  SC2200P50V2KX-2DLGP  [C402H22]  214.78 65.84 270 top
C2604  SC4D7U6D3V3KX-DLGP  [C603H36]  220.87 69.24 0 bottom
C2605  SCD1U16V2KX-3DLGP  [C402H22]  214.78 66.6 270 top
C2606  SC470P50V3JN-2GP  [C603H36]  168.8 103.79 90 bottom
C2607  SC2200P50V2KX-2GP  [C402H22]  170.53 104.96 90 bottom
C2608  SCD1U16V2KX-3DLGP  [C402H22]  165.2 103.46 180 top
C2609  SCD1U16V2KX-3DLGP  [C402H22]  164.41 103.43 180 top
C2610  SCD1U16V2KX-3DLGP  [C402H22]  24.81 42.62 180 top
C2612  SCD1U16V2KX-3DLGP  [C402H22]  59.23 45.42 90 top
C2613  SC100P50V2JN-3DLGP  [C402H22]  59.23 46.18 90 top
C2702  SC2D2U10V3KX-L-GP  [C603H36]  17.32 19.46 90 top
C2703  SC2D2U10V3KX-L-GP  [C603H36]  18 21.39 0 bottom
C2704  SCD1U16V2KX-3GP  [C402H22]  18.92 15.62 0 bottom
C2705  SC2D2U10V3KX-L-GP  [C603H36]  22.37 14.89 270 bottom
C2706  SCD1U16V2KX-3GP  [C402H22]  19.68 20.88 180 top
C2707  SC10U6D3V3MX-GP  [C603H38]  18 21.39 180 top
C2708  SC2D2U10V3KX-L-GP  [C603H36]  19.55 14.61 180 top
C2709  SC2D2U10V3KX-L-GP  [C603H36]  17.72 15.17 90 top
C2710  SC10U6D3V3MX-GP  [C603H38]  18.46 11.36 270 top
C2711  SC10U6D3V3MX-GP  [C603H38]  18.46 12.63 270 top
C2713  SC10U6D3V3MX-GP  [C603H38]  24.81 13.41 90 bottom
C2714  SCD1U16V2KX-3GP  [C402H22]  25.7 14.43 90 bottom
C2715  SC10U6D3V3MX-GP  [C603H38]  20.21 22.61 90 bottom
C2717  SC10U6D3V3MX-GP  [C603H38]  25.09 9.32 90 top
C2718  SCD1U16V2KX-3GP  [C402H22]  24.71 10.37 90 top
C2720  SC10U6D3V3MX-GP  [C603H38]  29.59 18.19 90 top
C2721  SCD1U16V2KX-3GP  [C402H22]  26.36 16.79 90 bottom
C2722  SC10U6D3V3MX-GP  [C603H38]  31.9 14.48 90 top
C2723  SC4D7U6D3V3KX-DLGP  [C603H36]  29.59 16.92 90 top
C2735  SCD1U16V2KX-3GP  [C402H22]  26.49 19.76 0 top
C2736  SCD1U16V2KX-3GP  [C402H22]  18.66 13.16 90 bottom
C2737  SCD1U16V2KX-3GP  [C402H22]  60.5 55.4 90 top
C2738  SCD22U10V2KX-L1-GP  [C402H22]  61.36 53.29 90 top
C2739  SC100P50V3JN-2GP  [C603H36]  24.63 21.87 180 top
C2740  SC2D2U10V3KX-L-GP  [C603H36]  29.61 16.51 270 bottom
C2741  SCD1U16V2KX-3GP  [C402H22]  26.33 15.19 90 bottom
C2902  SC10U6D3V3MX-GP  [C603H38]  16.07 11.53 270 top
C2907  SC4D7U6D3V3KX-DLGP  [C603H36]  20.71 21.48 180 top
C2908  SC4D7U6D3V3KX-DLGP  [C603H36]  21.98 21.48 180 top
C3401  SCD1U16V2KX-3DLGP  [C402H22]  218.48 38.38 0 top
C3402  SC1U10V2KX-1DLGP  [C402H22]  221.89 38.41 0 top
C3403  SC22U6D3V3MX-1-DL-GP  [C603H40]  220.82 38.43 0 top
C3404  SC22U6D3V3MX-1-DL-GP  [C603H40]  219.53 38.43 0 top
C3422  SC1U10V2KX-1DLGP  [C402H22]  22.24 30.48 0 top
C3506  SC22U6D3V3MX-1-DL-GP  [C603H40]  23.36 26.19 180 bottom
C3507  SC1U10V2KX-1DLGP  [C402H22]  16.43 53.7 180 bottom
C3508  SCD1U16V2KX-3DLGP  [C402H22]  15.16 33.86 270 top
C3509  SC22U6D3V3MX-1-DL-GP  [C603H40]  16.48 30.97 270 top
C3510  SC1U10V2KX-1DLGP  [C402H22]  23.16 28.12 0 bottom
C3511  SCD1U16V2KX-3DLGP  [C402H22]  21.91 26.85 270 top
C3512  SCD1U16V2KX-3DLGP  [C402H22]  21.91 27.61 270 top
C3514  SCD1U16V2KX-3DLGP  [C402H22]  20.95 44.63 90 bottom
C3516  SCD1U16V2KX-3DLGP  [C402H22]  17.39 50.96 0 bottom
C3517  SC1U10V2KX-1DLGP  [C402H22]  16.43 50.96 0 bottom
C3518  SC22U6D3V3MX-1-DL-GP  [C603H40]  17.95 47.65 180 bottom
C3519  SC22U6D3V3MX-1-DL-GP  [C603H40]  16.68 47.65 180 bottom
C3520  SCD1U16V2KX-3DLGP  [C402H22]  20.95 45.42 90 bottom
C3601  SC1U10V2KX-1DLGP  [C402H22]  21.74 35.66 0 bottom
C3602  SCD1U16V2KX-3DLGP  [C402H22]  23.01 30.48 0 top
C3603  SCD1U16V2KX-3DLGP  [C402H22]  20.95 35.66 0 bottom
C3604  SC22U6D3V3MX-1-DL-GP  [C603H40]  16.48 32.24 270 top
C3605  SC22U6D3V3MX-1-DL-GP  [C603H40]  24.25 29.85 0 bottom
C4001  SC470P50V2KX-3DLGP  [C402H22]  210.99 50.7 90 top
C4005  SC10U6D3V3MX-DL-GP  [C603H36]  209.11 47.5 0 top
C4006  SC10U6D3V3MX-DL-GP  [C603H36]  211.25 37.57 90 top
C4007  SCD1U25V2KX-1-DL-GP  [C402H22]  160.93 60.48 270 bottom
C4008  SC10U6D3V3MX-GP  [C603H38]  164.79 65.31 270 bottom
C4009  SC10U6D3V3MX-DL-GP  [C603H36]  203.3 54.71 180 top
C4010  SC470P50V2KX-3DLGP  [C402H22]  211.88 38.69 90 top
C4011  SCD1U25V2KX-1-DL-GP  [C402H22]  162.66 65.26 90 bottom
C4012  SC10U6D3V3MX-GP  [C603H38]  107.94 105.54 0 bottom
C4013  SC10U6D3V3MX-GP  [C603H38]  110.51 106.43 90 bottom
C4014  SCD1U25V2KX-1-DL-GP  [C402H22]  210.66 43.69 270 top
C4031  SC1U10V2KX-1GP  [C402H22]  113.8 103.65 270 bottom
C4032  SC1U10V2KX-1GP  [C402H22]  160.7 66.5 0 bottom
C4033  SCD1U25V2KX-1-DL-GP  [C402H22]  161.06 67.62 90 bottom
C4034  SC1U10V2KX-1GP  [C402H22]  110 101.45 0 bottom
C4035  SC22U6D3V3MX-1-DL-GP  [C603H40]  159.02 68.18 90 bottom
C4036  SC22U6D3V3MX-1-DL-GP  [C603H40]  159.02 66.89 90 bottom
C4041  SC1U10V2KX-1GP  [C402H22]  164.74 62.44 270 top
C4043  SC1U10V2KX-1GP  [C402H22]  164.87 66.35 270 bottom
C4045  SC10U6D3V3MX-GP  [C603H38]  158.97 65.61 90 bottom
C4047  SCD1U25V2KX-1-DL-GP  [C402H22]  166.06 61.29 180 bottom
C4301  SC1U25V3KX-1-DLGP  [C603H36]  29.61 88.17 0 top
C4302  SCD1U50V3KX-DL-GP  [C603H35]  35.45 88.32 90 top
C4303  SCD01U50V2KX-1DLGP  [C402H22]  39.52 85.27 90 top
C4304  SCD01U50V2KX-1DLGP  [C402H22]  39.52 86.03 90 top
C4305  SCD01U50V2KX-1DLGP  [C402H22]  39.52 84.48 90 top
C4306  SC10U25V3MX-GP  [C603H40]  36.32 86.46 180 top
C4343  SC1500P50V2KX-2GP  [C402H22]  42.18 77.8 0 top
C4344  SC1KP50V2KX-1DLGP  [C402H22]  36.44 81.31 270 bottom
C5501  SCD1U16V2KX-3DLGP  [C402H22]  60.94 93.11 180 top
C5502  SC10U6D3V3MX-GP  [C603H38]  59.9 93 180 top
C5503  SC10U10V5KX-2GP  [C805H54]  58.24 89.33 270 bottom
C5505  SC4D7U6D3V3KX-DLGP  [C603H36]  45.36 79.15 0 bottom
C5508  SCD1U16V2KX-3DLGP  [C402H22]  45.76 89.49 0 bottom
C5514  SC2D2U25V3KX-1-GP  [C603H40]  47.11 94.39 90 top
C5515  SC1KP50V2KX-1DLGP  [C402H22]  36.87 91.24 270 top
C5518  SC2D2U25V3KX-1-GP  [C603H40]  40.99 91.29 270 top
C5531  SCD1U16V2KX-3DLGP  [C402H22]  41.73 88.72 0 bottom
C5532  SCD1U16V2KX-3DLGP  [C402H22]  46.53 89.49 0 bottom
C5533  SCD1U16V2KX-3DLGP  [C402H22]  42.49 88.72 0 bottom
C5534  SCD1U16V2KX-3DLGP  [C402H22]  44.24 89.49 0 bottom
C5535  SCD1U50V3KX-DL-GP  [C603H35]  36.87 92.28 270 top
C5536  SC1U10V2KX-1DLGP  [C402H22]  37.48 88.17 90 bottom
C5537  SCD1U16V2KX-3DLGP  [C402H22]  45 89.49 0 bottom
C5538  SCD1U16V2KX-3DLGP  [C402H22]  37.48 87.4 90 bottom
C5539  SC4D7U6D3V3KX-DLGP  [C603H36]  53.44 92.38 90 top
C5540  SC10P50V2JN-4DLGP  [C402H22]  53.31 87.35 180 bottom
C5541  SC10P50V2JN-4DLGP  [C402H22]  54.1 85.12 180 bottom
C5542  SC10U10V5KX-2GP  [C805H54]  66.75 90.83 180 bottom
C5550  SC10U10V5KX-2GP  [C805H54]  65.12 93.32 90 bottom
C5599  SC4D7U6D3V3KX-DLGP  [C603H36]  37.64 89.18 90 bottom
C5701  SCD1U16V2KX-3DLGP  [C402H22]  20.97 60.35 90 bottom
C5702  SCD1U16V2KX-3DLGP  [C402H22]  14.07 71.73 0 bottom
C5703  SCD1U16V2KX-3DLGP  [C402H22]  20.97 61.17 90 bottom
C5704  SCD1U16V2KX-3DLGP  [C402H22]  20.97 59.59 90 bottom
C5705  SCD1U16V2KX-3DLGP  [C402H22]  20.97 61.95 90 bottom
C5706  SCD1U16V2KX-3DLGP  [C402H22]  20.98 58.03 90 bottom
C5707  SCD1U16V2KX-3DLGP  [C402H22]  20.97 58.8 90 bottom
C5708  SCD1U16V2KX-3DLGP  [C402H22]  20.97 57.25 90 bottom
C5709  SCD1U16V2KX-3DLGP  [C402H22]  20.97 56.49 90 bottom
C6001  SCD1U16V2KX-3DLGP  [C402H22]  184.47 14.28 180 top
C6002  SC10U6D3V3MX-DL-GP  [C603H36]  184.78 14.68 270 bottom
C6003  SCD01U50V2KX-1DLGP  [C402H22]  195.9 19.54 180 bottom
C6004  SCD01U50V2KX-1DLGP  [C402H22]  195.12 19.54 180 bottom
C6005  SCD01U50V2KX-1DLGP  [C402H22]  193.55 19.53 180 bottom
C6006  SCD01U50V2KX-1DLGP  [C402H22]  194.34 19.53 180 bottom
C6007  SCD1U16V2KX-3DLGP  [C402H22]  188.31 13.41 90 top
C6008  SC10U6D3V3MX-DL-GP  [C603H36]  186.86 15.93 0 bottom
C6101  SCD1U16V2KX-3DLGP  [C402H22]  215.06 54.08 90 top
C6103  SCD1U16V2KX-3DLGP  [C402H22]  24.78 58.78 0 top
C6104  SCD1U16V2KX-3DLGP  [C402H22]  220.95 58.47 270 top
C6106  SC10U25V5KX-DL-GP  [C805H58]  190.75 50.04 90 bottom
C6107  SCD1U16V2KX-3DLGP  [C402H22]  204.62 62.92 0 bottom
C6108  SCD1U16V2KX-3DLGP  [C402H22]  205.38 62.92 0 bottom
C6109  SCD1U25V2KX-1-DL-GP  [C402H22]  212.39 54.38 270 top
C6110  SCD1U25V2KX-1-DL-GP  [C402H22]  212.39 55.17 270 top
C6302  SCD22U10V2KX-2-GP  [C402H22]  198.62 17.58 0 bottom
C6303  SCD22U10V2KX-2-GP  [C402H22]  199.38 17.58 0 bottom
C6304  SC33P50V2JN-3DLGP  [C402H22]  216.83 22.43 180 top
C6305  SC33P50V2JN-3DLGP  [C402H22]  218.36 22.43 180 top
